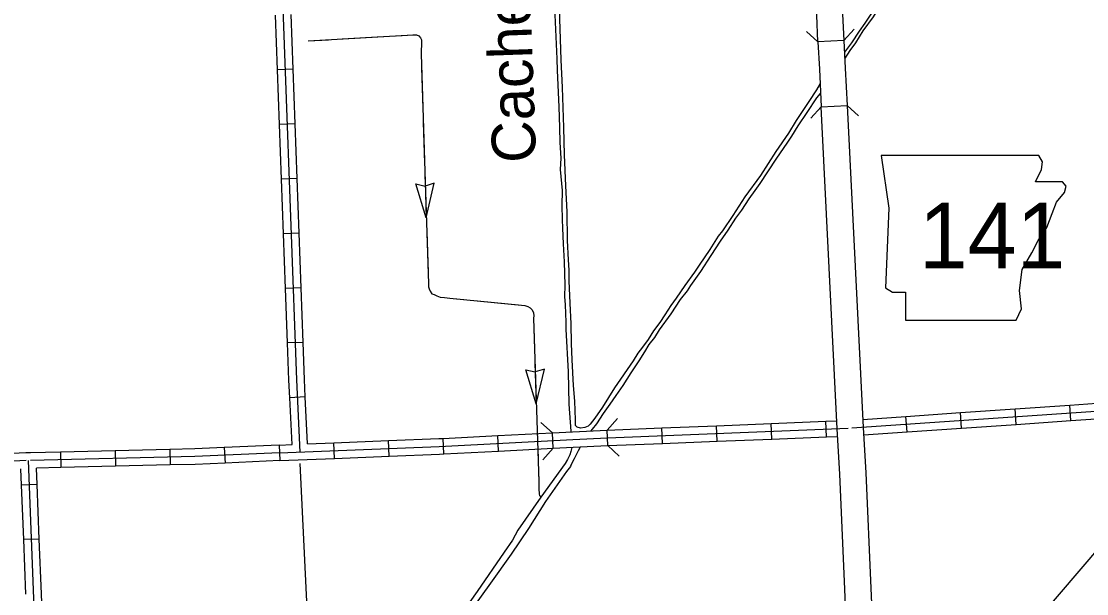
# Model space of a CAD drawing. Extents: x -5566 to 1759129, y -3726 to 731467.
# Drawn here: x -4760.4 to -4682.4, y 465.2 to 507.2 of the extents above; entities that cross this region are included whole.
import ezdxf

# ---------------------------------------------------------------- set-up
doc = ezdxf.new("R2010")
doc.units = 0
doc.layers.add('Default', color=7, linetype='Continuous')

msp = doc.modelspace()

# ---------------------------------------------------------------- linework, layer by layer
at = {"layer": 'Default'}
for p, q in [((-4740.532, 503.69), (-4741.67, 503.648)), ((-4740.384, 499.683), (-4741.523, 499.641)), ((-4740.237, 495.676), (-4741.375, 495.634)), ((-4730.773, 492.78), (-4731.532, 495.273)), ((-4731.532, 495.273), (-4730.856, 495.116)), ((-4730.184, 495.319), (-4730.847, 495.116)), ((-4730.773, 492.78), (-4730.184, 495.319)), ((-4740.089, 491.669), (-4741.228, 491.627)), ((-4739.942, 487.662), (-4741.08, 487.62)), ((-4739.794, 483.655), (-4740.933, 483.613)), ((-4722.715, 479.163), (-4723.47, 481.657)), ((-4723.47, 481.657), (-4722.794, 481.499)), ((-4722.121, 481.7), (-4722.785, 481.5)), ((-4722.715, 479.163), (-4722.121, 481.7)), ((-4739.633, 479.655), (-4740.771, 479.6)), ((-4691.552, 477.371), (-4691.63, 478.507)), ((-4687.552, 477.647), (-4687.63, 478.784)), ((-4683.551, 477.924), (-4683.63, 479.061)), ((-4705.461, 476.574), (-4705.507, 477.713)), ((-4701.455, 476.736), (-4701.501, 477.874)), ((-4695.552, 477.094), (-4695.631, 478.23)), ((-4721.479, 475.893), (-4721.538, 477.03)), ((-4717.476, 476.089), (-4717.531, 477.227)), ((-4713.474, 476.251), (-4713.52, 477.389)), ((-4709.468, 476.413), (-4709.514, 477.551)), ((-4741.561, 476.125), (-4741.512, 474.987)), ((-4737.507, 475.151), (-4737.553, 476.289)), ((-4733.5, 475.315), (-4733.547, 476.453)), ((-4729.488, 475.483), (-4729.547, 476.62)), ((-4725.484, 475.688), (-4725.542, 476.825)), ((-4757.58, 475.622), (-4757.553, 474.484)), ((-4753.572, 475.717), (-4753.545, 474.579)), ((-4749.563, 475.812), (-4749.536, 474.674)), ((-4745.567, 475.95), (-4745.518, 474.812)), ((-4759.278, 473.247), (-4760.417, 473.202)), ((-4759.121, 469.24), (-4760.259, 469.196))]:
    msp.add_line(p, q, dxfattribs=at)
for points in [[(-4813.759, 313.857), (-4581.459, 585.645), (-4581.459, 585.645)], [(-4740.01, 475.622), (-4740.263, 480.917), (-4741.511, 514.814)], [(-4721.504, 511.998), (-4721.443, 509.853), (-4721.208, 504.435), (-4721.19, 503.581), (-4721.063, 500.923), (-4721.017, 499.412), (-4720.998, 498.314), (-4720.92, 497.152), (-4720.968, 496.334), (-4720.826, 494.792), (-4720.833, 493.7), (-4720.806, 492.668), (-4720.794, 492.027), (-4720.744, 490.873), (-4720.682, 489.554), (-4720.611, 487.856), (-4720.651, 487.023), (-4720.607, 486.401), (-4720.544, 485.136), (-4720.559, 484.63), (-4720.368, 481.503), (-4720.323, 479.118), (-4720.181, 477.159), (-4720.177, 477.1)], [(-4721.193, 511.899), (-4721.074, 508.911), (-4720.92, 504.379), (-4720.829, 502.35), (-4720.729, 499.418), (-4720.682, 497.415), (-4720.567, 495.131), (-4720.482, 493.223), (-4720.444, 491.136), (-4720.381, 489.708), (-4720.326, 488.953), (-4720.331, 488.168), (-4720.244, 486.527), (-4720.181, 485.023), (-4720.156, 483.571), (-4720.098, 482.368), (-4720.011, 480.487), (-4719.917, 479.34), (-4719.876, 477.991), (-4719.859, 477.598)], [(-4702.076, 505.692), (-4702.172, 507.657), (-4702.283, 511.896), (-4702.283, 511.896)], [(-4700.385, 511.94), (-4700.385, 511.94), (-4700.274, 507.719), (-4700.18, 505.785), (-4702.076, 505.692)], [(-4695.33, 511.976), (-4695.632, 511.509), (-4696.149, 510.754), (-4696.694, 509.985), (-4696.959, 509.566), (-4697.56, 508.671), (-4698.203, 507.721), (-4698.65, 507.064), (-4699.069, 506.477), (-4699.628, 505.625), (-4700.138, 504.925)], [(-4700.114, 504.437), (-4699.726, 505.044), (-4699.293, 505.617), (-4698.762, 506.498), (-4698.007, 507.532), (-4697.428, 508.467), (-4697.253, 508.733), (-4696.931, 509.195), (-4696.708, 509.544), (-4696.428, 509.949), (-4695.967, 510.611), (-4695.548, 511.24), (-4695.032, 511.979)], [(-4741.67, 503.648), (-4741.818, 507.655)], [(-4740.532, 503.69), (-4740.68, 507.697)], [(-4699.415, 506.629), (-4700.18, 505.785)], [(-4739.427, 505.756), (-4731.765, 506.194), (-4731.492, 506.198), (-4731.314, 506.122), (-4731.194, 505.989), (-4731.128, 505.847), (-4731.112, 505.657), (-4731.133, 505.435), (-4731.148, 505.068), (-4731.143, 504.778), (-4730.863, 495.428), (-4730.608, 487.946), (-4730.606, 487.732), (-4730.569, 487.574), (-4730.487, 487.417), (-4730.357, 487.224), (-4730.203, 487.162), (-4730.009, 487.063), (-4729.747, 486.983), (-4729.427, 486.95), (-4729.052, 486.898), (-4723.547, 486.359), (-4723.331, 486.284), (-4723.152, 486.185), (-4723.01, 486.046), (-4722.924, 485.821), (-4722.901, 485.616), (-4722.916, 485.44), (-4722.532, 473.454), (-4722.53, 473.233), (-4722.536, 473.011), (-4722.52, 472.821), (-4722.513, 472.654), (-4722.501, 472.532), (-4722.482, 472.441), (-4722.441, 472.382), (-4722.388, 472.304)], [(-4739.427, 505.756), (-4737.926, 505.842)], [(-4736.925, 505.899), (-4733.923, 506.071)], [(-4732.922, 506.128), (-4731.765, 506.194), (-4731.492, 506.198), (-4731.314, 506.122), (-4731.194, 505.989), (-4731.128, 505.847), (-4731.112, 505.657), (-4731.133, 505.435), (-4731.148, 505.068), (-4731.144, 504.803)], [(-4702.076, 505.692), (-4702.92, 506.457)], [(-4700.18, 505.785), (-4700.081, 503.772), (-4699.945, 501.027)], [(-4702.076, 505.692), (-4701.978, 503.678), (-4701.841, 500.932)], [(-4741.523, 499.641), (-4741.67, 503.648)], [(-4740.384, 499.683), (-4740.532, 503.69)], [(-4731.114, 503.801), (-4731.024, 500.795)], [(-4701.926, 502.639), (-4702.185, 502.165), (-4702.744, 501.326), (-4703.666, 499.914), (-4704.239, 498.992)], [(-4704.002, 498.768), (-4703.527, 499.523), (-4702.87, 500.501), (-4702.171, 501.592), (-4701.889, 501.906)], [(-4702.605, 500.088), (-4701.841, 500.932)], [(-4698.814, 431.315), (-4698.721, 432.115), (-4698.675, 432.867), (-4698.778, 434.139), (-4698.721, 435.445), (-4698.595, 436.159), (-4698.227, 437.302), (-4698.089, 437.971), (-4697.988, 438.285), (-4697.955, 438.462), (-4697.948, 438.785), (-4697.992, 439.111), (-4698.13, 439.835), (-4698.355, 440.669), (-4698.622, 441.807), (-4698.882, 442.834), (-4699.073, 443.884), (-4699.231, 445.15), (-4699.321, 446.492), (-4699.735, 457.104), (-4700.479, 474.003), (-4700.664, 477.326), (-4701.841, 500.932), (-4699.945, 501.027)], [(-4699.945, 501.027), (-4698.768, 477.426), (-4698.583, 474.098), (-4697.838, 457.183), (-4697.425, 446.593), (-4697.34, 445.332), (-4697.195, 444.172), (-4697.026, 443.237), (-4696.778, 442.257), (-4696.514, 441.134), (-4696.279, 440.261), (-4696.117, 439.416), (-4696.046, 438.889), (-4696.061, 438.265), (-4696.144, 437.82), (-4696.25, 437.487), (-4696.389, 436.818), (-4696.748, 435.701), (-4696.829, 435.238), (-4696.876, 434.174), (-4696.772, 432.885), (-4696.829, 431.947), (-4696.928, 431.096)], [(-4699.945, 501.027), (-4699.1, 500.263)], [(-4741.375, 495.634), (-4741.523, 499.641)], [(-4740.237, 495.676), (-4740.384, 499.683)], [(-4730.994, 499.793), (-4730.903, 496.787)], [(-4704.239, 498.992), (-4705.154, 497.657), (-4706.29, 495.893), (-4707.439, 494.326), (-4708.327, 492.955), (-4709.084, 491.833), (-4709.384, 491.441), (-4709.991, 490.456), (-4710.775, 489.307), (-4711.127, 488.797), (-4711.832, 487.818), (-4712.459, 486.89), (-4712.851, 486.355), (-4713.295, 485.676), (-4713.673, 485.116), (-4714.117, 484.502), (-4714.509, 483.875), (-4714.927, 483.314), (-4715.266, 482.871), (-4715.619, 482.309), (-4716.995, 480.32), (-4717.857, 478.909), (-4718.431, 478.099), (-4718.761, 477.662)], [(-4718.697, 477.171), (-4718.601, 477.304), (-4718.275, 477.696), (-4717.791, 478.441), (-4717.295, 479.133), (-4716.864, 479.76), (-4716.347, 480.497), (-4715.76, 481.437), (-4715.185, 482.312), (-4714.768, 482.965), (-4714.441, 483.501), (-4714.023, 484.023), (-4713.684, 484.585), (-4712.835, 485.747), (-4712.143, 486.792), (-4711.634, 487.432), (-4711.386, 487.837), (-4710.668, 488.856), (-4709.902, 490.023), (-4709.223, 491.081), (-4708.648, 491.891), (-4708.087, 492.766), (-4707.656, 493.341), (-4707.121, 494.177), (-4706.69, 494.791), (-4706.311, 495.313), (-4705.14, 497.093), (-4704.291, 498.334), (-4704.002, 498.768)], [(-4741.228, 491.627), (-4741.375, 495.634)], [(-4740.089, 491.669), (-4740.237, 495.676)], [(-4730.873, 495.785), (-4730.863, 495.428), (-4730.773, 492.78)], [(-4730.738, 491.778), (-4730.687, 490.275)], [(-4741.08, 487.62), (-4741.228, 491.627)], [(-4739.942, 487.662), (-4740.089, 491.669)], [(-4730.687, 490.275), (-4730.636, 488.772)], [(-4740.933, 483.613), (-4741.08, 487.62)], [(-4739.794, 483.655), (-4739.942, 487.662)], [(-4730.607, 487.77), (-4730.606, 487.732), (-4730.569, 487.574), (-4730.487, 487.417), (-4730.357, 487.224), (-4730.203, 487.162), (-4730.009, 487.063), (-4729.747, 486.983), (-4729.427, 486.95), (-4729.052, 486.898), (-4728.018, 486.796)], [(-4727.021, 486.699), (-4724.028, 486.406)], [(-4723.09, 486.125), (-4723.01, 486.046), (-4722.924, 485.821), (-4722.901, 485.616), (-4722.916, 485.44), (-4722.843, 483.17)], [(-4740.771, 479.6), (-4740.833, 480.893), (-4740.933, 483.613)], [(-4739.633, 479.655), (-4739.694, 480.941), (-4739.794, 483.655)], [(-4722.811, 482.168), (-4722.715, 479.163)], [(-4740.606, 476.164), (-4740.771, 479.6)], [(-4739.468, 476.211), (-4739.633, 479.655)], [(-4683.63, 479.061), (-4680.339, 479.288), (-4679.618, 479.324)], [(-4699.591, 477.385), (-4680.305, 478.72)], [(-4695.631, 478.23), (-4691.63, 478.507)], [(-4691.63, 478.507), (-4687.63, 478.784)], [(-4687.63, 478.784), (-4683.63, 479.061)], [(-4722.683, 478.161), (-4722.645, 476.974)], [(-4722.383, 477.794), (-4721.538, 477.03)], [(-4718.761, 477.662), (-4718.922, 477.516), (-4719.154, 477.416), (-4719.47, 477.358), (-4719.719, 477.449), (-4719.859, 477.598)], [(-4717.528, 477.227), (-4716.759, 478.067)], [(-4709.514, 477.551), (-4705.507, 477.713)], [(-4705.507, 477.713), (-4701.501, 477.874)], [(-4701.501, 477.874), (-4700.693, 477.907)], [(-4698.798, 478.011), (-4695.631, 478.23)], [(-4687.552, 477.647), (-4683.551, 477.924)], [(-4683.551, 477.924), (-4680.271, 478.151), (-4679.562, 478.186)], [(-4725.542, 476.825), (-4721.538, 477.03)], [(-4721.538, 477.03), (-4720.063, 477.106), (-4717.531, 477.227)], [(-4720.035, 476.537), (-4717.5, 476.658), (-4699.862, 477.371)], [(-4717.53, 477.227), (-4717.525, 477.227), (-4713.52, 477.389)], [(-4713.52, 477.389), (-4709.514, 477.551)], [(-4698.738, 476.873), (-4695.552, 477.094)], [(-4695.552, 477.094), (-4691.552, 477.371)], [(-4691.552, 477.371), (-4687.552, 477.647)], [(-4741.561, 476.125), (-4745.567, 475.95)], [(-4741.561, 476.125), (-4740.606, 476.164)], [(-4741.536, 475.556), (-4729.82, 476.036), (-4720.035, 476.537)], [(-4739.468, 476.211), (-4737.553, 476.289)], [(-4737.553, 476.289), (-4733.547, 476.453)], [(-4733.547, 476.453), (-4729.846, 476.605), (-4729.547, 476.62)], [(-4729.547, 476.62), (-4725.542, 476.825)], [(-4717.477, 476.089), (-4717.475, 476.089), (-4713.474, 476.251)], [(-4713.474, 476.251), (-4709.468, 476.413)], [(-4709.468, 476.413), (-4705.461, 476.574)], [(-4705.461, 476.574), (-4701.455, 476.736)], [(-4701.455, 476.736), (-4700.633, 476.769)], [(-4757.58, 475.622), (-4759.775, 475.57), (-4760.112, 475.558), (-4761.603, 475.481)], [(-4741.536, 475.556), (-4747.717, 475.286), (-4759.758, 475.001)], [(-4753.572, 475.717), (-4757.58, 475.622)], [(-4749.563, 475.812), (-4753.572, 475.717)], [(-4745.567, 475.95), (-4747.736, 475.856), (-4749.563, 475.812)], [(-4737.507, 475.151), (-4733.5, 475.315)], [(-4733.5, 475.315), (-4729.794, 475.467), (-4729.488, 475.483)], [(-4729.488, 475.483), (-4725.484, 475.688)], [(-4720.118, 475.962), (-4720.194, 475.657), (-4720.246, 475.422), (-4720.35, 475.226), (-4720.429, 475.082), (-4720.599, 474.782), (-4722.388, 472.304), (-4724.06, 469.887), (-4724.462, 469.161), (-4725.078, 468.28), (-4727.052, 465.397), (-4728.406, 463.47)], [(-4725.484, 475.688), (-4721.479, 475.893)], [(-4722.608, 475.835), (-4722.586, 475.155)], [(-4721.479, 475.893), (-4722.243, 475.047)], [(-4721.479, 475.893), (-4720.007, 475.968), (-4717.476, 476.089)], [(-4720.178, 474.633), (-4719.92, 475.149), (-4719.619, 475.724), (-4719.482, 475.993)], [(-4716.639, 475.32), (-4717.479, 476.089)], [(-4760.086, 474.989), (-4769.705, 474.494), (-4779.76, 474.008), (-4783.246, 473.891), (-4795.373, 473.468), (-4799.278, 473.392), (-4811.135, 473.04), (-4817.672, 472.821), (-4819.193, 472.753)], [(-4758.108, 432.325), (-4758.323, 437.245), (-4758.639, 444.117), (-4758.892, 449.799), (-4759.134, 454.73), (-4759.22, 457.281), (-4759.917, 474.997)], [(-4753.545, 474.579), (-4757.553, 474.484)], [(-4749.536, 474.674), (-4753.545, 474.579)], [(-4745.518, 474.812), (-4747.697, 474.717), (-4749.536, 474.674)], [(-4741.512, 474.987), (-4745.518, 474.812)], [(-4741.512, 474.987), (-4737.507, 475.151)], [(-4740.036, 474.775), (-4738.76, 448.468)], [(-4720.178, 474.633), (-4720.217, 474.566), (-4720.497, 474.188), (-4722.03, 471.995), (-4723.29, 470.004), (-4724.563, 468.126), (-4726.067, 465.995), (-4727.56, 463.925)], [(-4760.417, 473.202), (-4760.464, 474.399)], [(-4757.553, 474.484), (-4759.325, 474.442)], [(-4759.278, 473.247), (-4759.325, 474.442)], [(-4722.554, 474.153), (-4722.532, 473.454), (-4722.53, 473.233), (-4722.536, 473.011), (-4722.52, 472.821), (-4722.513, 472.654), (-4722.513, 472.651)], [(-4760.259, 469.196), (-4760.417, 473.202)], [(-4759.121, 469.24), (-4759.278, 473.247)], [(-4722.513, 472.651), (-4722.501, 472.532), (-4722.482, 472.441), (-4722.441, 472.382), (-4722.388, 472.304)], [(-4760.101, 465.189), (-4760.259, 469.196)], [(-4758.963, 465.234), (-4759.121, 469.24)], [(-4758.805, 461.227), (-4758.963, 465.234)]]:
    msp.add_lwpolyline(points, dxfattribs=at)
msp.add_lwpolyline([(-4697.455, 497.353), (-4696.877, 493.498), (-4697.134, 487.653), (-4696.62, 487.331), (-4695.656, 487.331), (-4695.656, 485.276), (-4687.562, 485.276), (-4687.176, 486.111), (-4687.305, 487.46), (-4687.112, 489.002), (-4686.406, 490.222), (-4685.956, 491.121), (-4685.314, 492.085), (-4684.928, 493.113), (-4684.607, 493.948), (-4684.029, 494.655), (-4683.9, 495.104), (-4684.157, 495.425), (-4686.149, 495.425), (-4685.699, 496.325), (-4685.635, 496.903), (-4685.901, 497.347)], close=True, dxfattribs=at)

# ---------------------------------------------------------------- texts
msp.add_text('Cache', height=3.2048, rotation=92.01106, dxfattribs=at).set_placement((-4722.72, 496.874))
msp.add_text('141', height=4.8071, dxfattribs=at).set_placement((-4694.679, 489.085))

doc.saveas('drawing.dxf')
